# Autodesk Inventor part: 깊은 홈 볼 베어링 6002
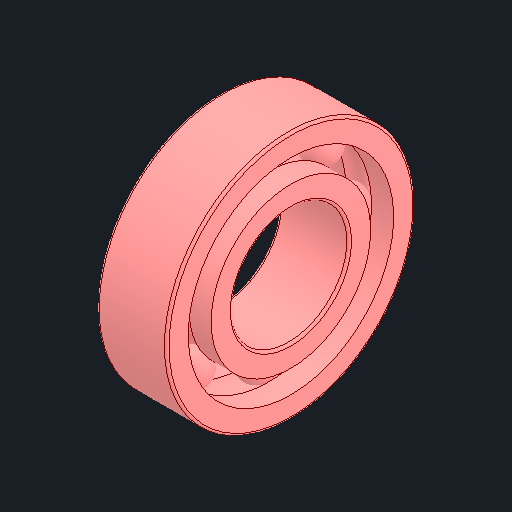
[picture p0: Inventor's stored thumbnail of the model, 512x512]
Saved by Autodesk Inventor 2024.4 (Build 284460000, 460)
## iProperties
Created: 2025-10
Part Number: 깊은 홈 볼 베어링 6002
Material: 강철, 연강
Description: 깊은 그루브 볼 베어링
Document SubType Name: Modeling
Designer: user
Density: 7.85 g/cm^3
Appearance: 기본값
Author: jhkim
Sending System: Autodesk Inventor 2026
Preprocessor: ST-DEVELOPER v20.1
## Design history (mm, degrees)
feature "Solid1"
feature "Solid1:1"
feature "Solid1:2"
feature "Solid1:3"
feature "Solid1:4"
feature "Solid1:5"
feature "Solid1:6"
feature "Solid1:7"
feature "Solid1:8"
feature "Solid1:9"
node "솔리드1"
node "솔리드2"
node "솔리드3"
node "솔리드4"
node "솔리드5"
node "솔리드6"
node "솔리드7"
node "솔리드8"
node "솔리드9"
node "솔리드10"
